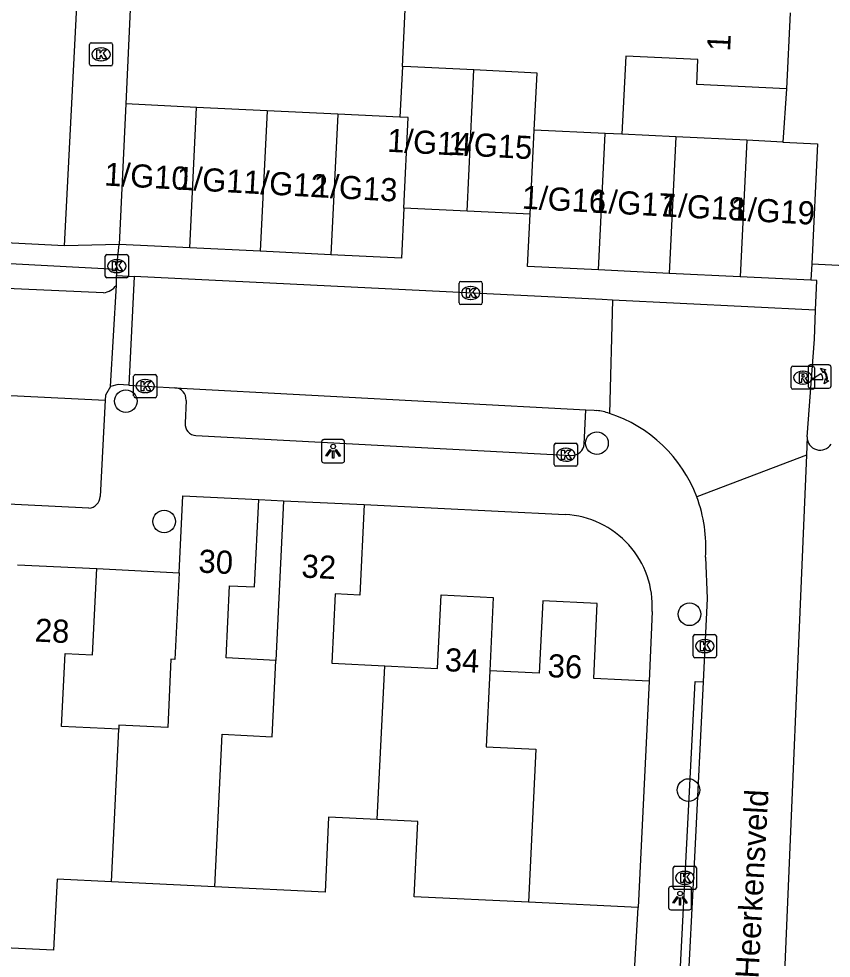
# Model space of a CAD drawing. Extents: x 162990 to 165007, y 383433 to 384336.
# Drawn here: x 164423.42 to 164458.56, y 383752.31 to 383792.95 of the extents above; entities that cross this region are included whole.
import ezdxf

# ---------------------------------------------------------------- set-up
doc = ezdxf.new("R2010")
doc.units = 0
for name, color, linetype in [('IMGEO_Boom', 7, 'Continuous'), ('IMGEO_Kolk', 7, 'Continuous'), ('IMGEO_Lichtpunt', 7, 'Continuous'), ('IMGEO_Muur', 7, 'Continuous'), ('IMGEO_Openbare_ruimte_label', 7, 'Continuous'), ('IMGEO_Pand', 7, 'Continuous'), ('IMGEO_Pand_nummerreeks', 7, 'Continuous'), ('IMGEO_Poller', 7, 'Continuous'), ('IMGEO_Rijbaan_lokaal_open', 7, 'Continuous'), ('IMGEO_Rioolput', 7, 'Continuous'), ('IMGEO_Voetpad_open', 7, 'Continuous')]:
    doc.layers.add(name, color=color, linetype=linetype)

msp = doc.modelspace()

# ---------------------------------------------------------------- linework, layer by layer
at = {"layer": 'IMGEO_Boom'}
for centre in [(164428.046, 383776.408), (164448.428, 383774.593), (164429.703, 383771.203), (164452.433, 383767.192), (164452.385, 383759.588)]:
    msp.add_circle(centre, 0.489, dxfattribs=at)
at = {"layer": 'IMGEO_Kolk'}
for p, q in [((164426.551, 383791.916), (164427.403, 383791.916)), ((164426.476, 383790.99), (164426.476, 383791.842)), ((164426.964, 383791.696), (164426.989, 383791.696)), ((164427.477, 383791.842), (164427.477, 383790.99)), ((164426.987, 383791.136), (164426.962, 383791.136)), ((164427.403, 383790.916), (164426.551, 383790.916)), ((164427.156, 383781.825), (164427.156, 383782.677)), ((164427.231, 383782.751), (164428.083, 383782.751)), ((164428.157, 383782.677), (164428.157, 383781.825)), ((164427.644, 383782.531), (164427.669, 383782.531)), ((164428.083, 383781.751), (164427.231, 383781.751)), ((164427.667, 383781.971), (164427.642, 383781.971)), ((164442.465, 383780.663), (164442.465, 383781.515)), ((164442.54, 383781.589), (164443.392, 383781.589)), ((164442.953, 383781.369), (164442.978, 383781.369)), ((164443.466, 383781.515), (164443.466, 383780.663)), ((164443.392, 383780.589), (164442.54, 383780.589)), ((164442.976, 383780.809), (164442.951, 383780.809)), ((164428.387, 383776.636), (164428.387, 383777.488)), ((164428.462, 383777.562), (164429.314, 383777.562)), ((164428.875, 383777.342), (164428.9, 383777.342)), ((164429.388, 383777.488), (164429.388, 383776.636)), ((164429.314, 383776.562), (164428.462, 383776.562)), ((164428.898, 383776.782), (164428.873, 383776.782)), ((164446.58, 383773.667), (164446.58, 383774.519)), ((164446.655, 383774.593), (164447.507, 383774.593)), ((164447.581, 383774.519), (164447.581, 383773.667)), ((164447.068, 383774.373), (164447.093, 383774.373)), ((164447.091, 383773.813), (164447.066, 383773.813)), ((164447.507, 383773.593), (164446.655, 383773.593)), ((164452.667, 383766.314), (164453.519, 383766.314)), ((164452.592, 383765.388), (164452.592, 383766.24)), ((164453.08, 383766.094), (164453.105, 383766.094)), ((164453.593, 383766.24), (164453.593, 383765.388)), ((164453.103, 383765.534), (164453.078, 383765.534)), ((164453.519, 383765.314), (164452.667, 383765.314)), ((164451.728, 383755.365), (164451.728, 383756.217)), ((164451.803, 383756.291), (164452.655, 383756.291)), ((164452.729, 383756.217), (164452.729, 383755.365)), ((164452.216, 383756.071), (164452.241, 383756.071)), ((164452.239, 383755.511), (164452.214, 383755.511)), ((164452.655, 383755.291), (164451.803, 383755.291))]:
    msp.add_line(p, q, dxfattribs=at)
for points in [[(164426.551, 383791.916), (164427.403, 383791.916)], [(164426.476, 383790.99), (164426.476, 383791.842)], [(164426.797, 383791.616), (164426.92, 383791.616), (164426.92, 383791.465), (164427.05, 383791.616), (164427.214, 383791.616), (164427.068, 383791.465), (164427.221, 383791.216), (164427.069, 383791.216), (164426.984, 383791.38), (164426.92, 383791.313), (164426.92, 383791.216), (164426.797, 383791.216), (164426.797, 383791.616)], [(164427.477, 383791.842), (164427.477, 383790.99)], [(164427.403, 383790.916), (164426.551, 383790.916)], [(164427.156, 383781.825), (164427.156, 383782.677)], [(164427.231, 383782.751), (164428.083, 383782.751)], [(164428.157, 383782.677), (164428.157, 383781.825)], [(164427.477, 383782.451), (164427.6, 383782.451), (164427.6, 383782.3), (164427.73, 383782.451), (164427.894, 383782.451), (164427.748, 383782.3), (164427.901, 383782.051), (164427.749, 383782.051), (164427.664, 383782.215), (164427.6, 383782.148), (164427.6, 383782.051), (164427.477, 383782.051), (164427.477, 383782.451)], [(164428.083, 383781.751), (164427.231, 383781.751)], [(164442.465, 383780.663), (164442.465, 383781.515)], [(164442.54, 383781.589), (164443.392, 383781.589)], [(164443.466, 383781.515), (164443.466, 383780.663)], [(164442.786, 383781.289), (164442.909, 383781.289), (164442.909, 383781.138), (164443.039, 383781.289), (164443.203, 383781.289), (164443.057, 383781.138), (164443.21, 383780.889), (164443.058, 383780.889), (164442.973, 383781.053), (164442.909, 383780.986), (164442.909, 383780.889), (164442.786, 383780.889), (164442.786, 383781.289)], [(164443.392, 383780.589), (164442.54, 383780.589)], [(164428.387, 383776.636), (164428.387, 383777.488)], [(164428.462, 383777.562), (164429.314, 383777.562)], [(164429.388, 383777.488), (164429.388, 383776.636)], [(164428.708, 383777.262), (164428.831, 383777.262), (164428.831, 383777.111), (164428.961, 383777.262), (164429.125, 383777.262), (164428.979, 383777.111), (164429.132, 383776.862), (164428.98, 383776.862), (164428.895, 383777.026), (164428.831, 383776.959), (164428.831, 383776.862), (164428.708, 383776.862), (164428.708, 383777.262)], [(164429.314, 383776.562), (164428.462, 383776.562)], [(164446.58, 383773.667), (164446.58, 383774.519)], [(164446.655, 383774.593), (164447.507, 383774.593)], [(164447.581, 383774.519), (164447.581, 383773.667)], [(164446.901, 383774.293), (164447.024, 383774.293), (164447.024, 383774.142), (164447.154, 383774.293), (164447.318, 383774.293), (164447.172, 383774.142), (164447.325, 383773.893), (164447.173, 383773.893), (164447.088, 383774.057), (164447.024, 383773.99), (164447.024, 383773.893), (164446.901, 383773.893), (164446.901, 383774.293)], [(164447.507, 383773.593), (164446.655, 383773.593)], [(164452.667, 383766.314), (164453.519, 383766.314)], [(164452.592, 383765.388), (164452.592, 383766.24)], [(164452.913, 383766.014), (164453.036, 383766.014), (164453.036, 383765.863), (164453.166, 383766.014), (164453.33, 383766.014), (164453.184, 383765.863), (164453.337, 383765.614), (164453.185, 383765.614), (164453.1, 383765.778), (164453.036, 383765.711), (164453.036, 383765.614), (164452.913, 383765.614), (164452.913, 383766.014)], [(164453.593, 383766.24), (164453.593, 383765.388)], [(164453.519, 383765.314), (164452.667, 383765.314)], [(164451.728, 383755.365), (164451.728, 383756.217)], [(164451.803, 383756.291), (164452.655, 383756.291)], [(164452.729, 383756.217), (164452.729, 383755.365)], [(164452.049, 383755.991), (164452.172, 383755.991), (164452.172, 383755.84), (164452.302, 383755.991), (164452.466, 383755.991), (164452.32, 383755.84), (164452.473, 383755.591), (164452.321, 383755.591), (164452.236, 383755.755), (164452.172, 383755.688), (164452.172, 383755.591), (164452.049, 383755.591), (164452.049, 383755.991)], [(164452.655, 383755.291), (164451.803, 383755.291)]]:
    msp.add_lwpolyline(points, dxfattribs=at)
for centre, start, end in [((164426.553, 383791.84), 91.552, 178.448), ((164426.553, 383791.84), 91.552, 178.448), ((164427.401, 383791.84), 1.552, 88.448), ((164427.401, 383791.84), 1.552, 88.448), ((164426.553, 383790.992), 181.552, 268.448), ((164426.553, 383790.992), 181.552, 268.448), ((164427.401, 383790.992), 271.552, 358.448), ((164427.401, 383790.992), 271.552, 358.448), ((164427.233, 383782.675), 91.552, 178.448), ((164427.233, 383782.675), 91.552, 178.448), ((164428.081, 383782.675), 1.552, 88.448), ((164428.081, 383782.675), 1.552, 88.448), ((164427.233, 383781.827), 181.552, 268.448), ((164427.233, 383781.827), 181.552, 268.448), ((164428.081, 383781.827), 271.552, 358.448), ((164428.081, 383781.827), 271.552, 358.448), ((164442.542, 383781.513), 91.552, 178.448), ((164442.542, 383781.513), 91.552, 178.448), ((164443.39, 383781.513), 1.552, 88.448), ((164443.39, 383781.513), 1.552, 88.448), ((164442.542, 383780.665), 181.552, 268.448), ((164442.542, 383780.665), 181.552, 268.448), ((164443.39, 383780.665), 271.552, 358.448), ((164443.39, 383780.665), 271.552, 358.448), ((164428.464, 383777.486), 91.552, 178.448), ((164428.464, 383777.486), 91.552, 178.448), ((164429.312, 383777.486), 1.552, 88.448), ((164429.312, 383777.486), 1.552, 88.448), ((164428.464, 383776.638), 181.552, 268.448), ((164428.464, 383776.638), 181.552, 268.448), ((164429.312, 383776.638), 271.552, 358.448), ((164429.312, 383776.638), 271.552, 358.448), ((164446.657, 383774.517), 91.552, 178.448), ((164446.657, 383774.517), 91.552, 178.448), ((164447.505, 383774.517), 1.552, 88.448), ((164447.505, 383774.517), 1.552, 88.448), ((164446.657, 383773.669), 181.552, 268.448), ((164446.657, 383773.669), 181.552, 268.448), ((164447.505, 383773.669), 271.552, 358.448), ((164447.505, 383773.669), 271.552, 358.448), ((164452.669, 383766.238), 91.552, 178.448), ((164452.669, 383766.238), 91.552, 178.448), ((164453.517, 383766.238), 1.552, 88.448), ((164453.517, 383766.238), 1.552, 88.448), ((164452.669, 383765.39), 181.552, 268.448), ((164452.669, 383765.39), 181.552, 268.448), ((164453.517, 383765.39), 271.552, 358.448), ((164453.517, 383765.39), 271.552, 358.448), ((164451.805, 383756.215), 91.552, 178.448), ((164451.805, 383756.215), 91.552, 178.448), ((164452.653, 383756.215), 1.552, 88.448), ((164452.653, 383756.215), 1.552, 88.448), ((164451.805, 383755.367), 181.552, 268.448), ((164451.805, 383755.367), 181.552, 268.448), ((164452.653, 383755.367), 271.552, 358.448), ((164452.653, 383755.367), 271.552, 358.448)]:
    msp.add_arc(centre, 0.0765, start, end, dxfattribs=at)
for centre, major_axis, ratio, start_param, end_param in [((164426.963, 383791.416), (-0.387, 0.002), 0.722429, 4.712389, 7.853982), ((164426.988, 383791.416), (-0.39, 0.002), 0.717154, 1.570796, 4.712389), ((164427.643, 383782.251), (-0.387, 0.002), 0.722429, 4.712389, 7.853982), ((164427.668, 383782.251), (-0.39, 0.002), 0.717154, 1.570796, 4.712389), ((164442.952, 383781.089), (-0.387, 0.002), 0.722429, 4.712389, 7.853982), ((164442.977, 383781.089), (-0.39, 0.002), 0.717154, 1.570796, 4.712389), ((164428.874, 383777.062), (-0.387, 0.002), 0.722429, 4.712389, 7.853982), ((164428.899, 383777.062), (-0.39, 0.002), 0.717154, 1.570796, 4.712389), ((164447.067, 383774.093), (-0.387, 0.002), 0.722429, 4.712389, 7.853982), ((164447.092, 383774.093), (-0.39, 0.002), 0.717154, 1.570796, 4.712389), ((164453.079, 383765.814), (-0.387, 0.002), 0.722429, 4.712389, 7.853982), ((164453.104, 383765.814), (-0.39, 0.002), 0.717154, 1.570796, 4.712389), ((164452.215, 383755.791), (-0.387, 0.002), 0.722429, 4.712389, 7.853982), ((164452.24, 383755.791), (-0.39, 0.002), 0.717154, 1.570796, 4.712389)]:
    msp.add_ellipse(centre, major_axis=major_axis, ratio=ratio, start_param=start_param, end_param=end_param, dxfattribs=at)
at = {"layer": 'IMGEO_Lichtpunt'}
for p, q in [((164436.516, 383774.651), (164436.516, 383773.844)), ((164436.516, 383774.651), (164436.516, 383773.844)), ((164437.418, 383774.746), (164436.61, 383774.746)), ((164437.418, 383774.746), (164436.61, 383774.746)), ((164437.512, 383773.844), (164437.512, 383774.651)), ((164437.512, 383773.844), (164437.512, 383774.651)), ((164436.61, 383773.75), (164437.418, 383773.75)), ((164436.61, 383773.75), (164437.418, 383773.75)), ((164452.427, 383755.409), (164451.619, 383755.409)), ((164452.427, 383755.409), (164451.619, 383755.409)), ((164451.525, 383755.314), (164451.525, 383754.507)), ((164451.525, 383755.314), (164451.525, 383754.507)), ((164452.521, 383754.507), (164452.521, 383755.314)), ((164452.521, 383754.507), (164452.521, 383755.314)), ((164451.619, 383754.413), (164452.427, 383754.413)), ((164451.619, 383754.413), (164452.427, 383754.413))]:
    msp.add_line(p, q, dxfattribs=at)
for points in [[(164436.89, 383774.315), (164436.929, 383774.287), (164436.741, 383774.025), (164436.703, 383774.052), (164436.89, 383774.315)], [(164436.992, 383774.267), (164437.039, 383774.267), (164437.039, 383773.945), (164436.992, 383773.945), (164436.992, 383774.267)], [(164437.102, 383774.287), (164437.14, 383774.314), (164437.327, 383774.052), (164437.288, 383774.024), (164437.102, 383774.287)], [(164451.899, 383754.978), (164451.938, 383754.95), (164451.75, 383754.688), (164451.712, 383754.715), (164451.899, 383754.978)], [(164452.001, 383754.93), (164452.048, 383754.93), (164452.048, 383754.608), (164452.001, 383754.608), (164452.001, 383754.93)], [(164452.111, 383754.95), (164452.149, 383754.977), (164452.336, 383754.715), (164452.297, 383754.687), (164452.111, 383754.95)]]:
    msp.add_lwpolyline(points, dxfattribs=at)
for centre in [(164437.015, 383774.449), (164452.024, 383755.112)]:
    msp.add_circle(centre, 0.0994, dxfattribs=at)
for centre, start, end in [((164436.61, 383774.651), 90, 180), ((164436.61, 383774.651), 90, 180), ((164437.418, 383774.651), 0, 90), ((164437.418, 383774.651), 0, 90), ((164436.61, 383773.844), 180, 270), ((164436.61, 383773.844), 180, 270), ((164437.418, 383773.844), 270, 0), ((164437.418, 383773.844), 270, 360), ((164451.619, 383755.314), 90, 180), ((164451.619, 383755.314), 90, 180), ((164452.427, 383755.314), 0, 90), ((164452.427, 383755.314), 0, 90), ((164451.619, 383754.507), 180, 270), ((164451.619, 383754.507), 180, 270), ((164452.427, 383754.507), 270, 0), ((164452.427, 383754.507), 270, 360)]:
    msp.add_arc(centre, 0.0946, start, end, dxfattribs=at)
at = {"layer": 'IMGEO_Muur'}
for points in [[(164448.304, 383707.855), (164448.207, 383705.364), (164447.887, 383705.375), (164448.047, 383709.634), (164444.948, 383709.752), (164445.705, 383725.181), (164445.823, 383727.577), (164446.336, 383738.034), (164448.318, 383737.931), (164451.313, 383737.776), (164451.421, 383739.875), (164451.942, 383750), (164452.677, 383764.285), (164453.018, 383764.265)], [(164453.018, 383764.265), (164452.659, 383756.974), (164452.307, 383750), (164452.117, 383746.236)]]:
    msp.add_lwpolyline(points, dxfattribs=at)
at = {"layer": 'IMGEO_Pand'}
for points in [[(164440.011, 383790.885), (164440.251, 383795.847)], [(164456.792, 383793.213), (164456.633, 383789.929)], [(164456.633, 383789.929), (164452.745, 383790.117), (164452.797, 383791.191), (164449.67, 383791.342), (164449.505, 383787.957)], [(164440.011, 383790.885), (164439.905, 383788.696)], [(164443.101, 383790.738), (164440.374, 383790.868), (164440.011, 383790.885)], [(164442.81, 383784.635), (164443.101, 383790.738)], [(164445.716, 383788.136), (164445.836, 383790.608), (164443.101, 383790.738)], [(164428.052, 383789.269), (164427.758, 383783.191)], [(164431.106, 383789.121), (164428.052, 383789.269)], [(164430.812, 383783.044), (164431.106, 383789.121)], [(164434.16, 383788.974), (164431.106, 383789.121)], [(164434.16, 383788.974), (164433.866, 383782.896)], [(164437.214, 383788.826), (164434.16, 383788.974)], [(164437.214, 383788.826), (164436.92, 383782.748)], [(164439.905, 383788.696), (164437.214, 383788.826)], [(164440.079, 383784.767), (164440.268, 383788.678), (164439.905, 383788.696)], [(164445.54, 383784.503), (164445.716, 383788.136)], [(164448.779, 383787.991), (164445.716, 383788.136)], [(164448.493, 383782.086), (164448.779, 383787.991)], [(164449.505, 383787.957), (164448.779, 383787.991)], [(164451.842, 383787.844), (164449.505, 383787.957)], [(164451.842, 383787.844), (164451.556, 383781.938)], [(164454.905, 383787.696), (164451.842, 383787.844)], [(164454.905, 383787.696), (164454.62, 383781.79)], [(164456.468, 383787.62), (164454.905, 383787.696)], [(164456.468, 383787.62), (164457.968, 383787.548), (164457.717, 383782.349)], [(164440.079, 383784.767), (164439.974, 383782.601), (164436.92, 383782.748)], [(164442.81, 383784.635), (164440.079, 383784.767)], [(164445.54, 383784.503), (164442.81, 383784.635)], [(164448.493, 383782.086), (164445.43, 383782.234), (164445.54, 383784.503)], [(164430.812, 383783.044), (164427.758, 383783.191)], [(164433.866, 383782.896), (164430.812, 383783.044)], [(164436.92, 383782.748), (164433.866, 383782.896)], [(164457.717, 383782.349), (164457.683, 383781.642)], [(164451.556, 383781.938), (164448.493, 383782.086)], [(164454.62, 383781.79), (164451.556, 383781.938)], [(164457.683, 383781.642), (164454.62, 383781.79)], [(164430.353, 383768.988), (164430.514, 383772.316), (164433.798, 383772.157)], [(164434.539, 383765.198), (164432.387, 383765.302), (164432.538, 383768.427), (164433.615, 383768.375), (164433.798, 383772.157)], [(164434.873, 383772.105), (164434.539, 383765.198)], [(164434.873, 383772.105), (164438.364, 383771.936)], [(164438.364, 383771.936), (164438.174, 383768.018), (164437.104, 383768.07), (164436.959, 383765.074), (164439.248, 383764.963)], [(164423.364, 383769.334), (164426.791, 383769.168)], [(164427.744, 383762.219), (164425.267, 383762.339), (164425.419, 383765.489), (164426.61, 383765.432), (164426.791, 383769.168)], [(164430.353, 383768.988), (164430.171, 383765.236), (164430.001, 383765.244), (164429.858, 383762.287), (164427.752, 383762.389), (164427.744, 383762.219)], [(164439.248, 383764.963), (164441.533, 383764.852), (164441.687, 383768.026), (164443.944, 383767.916), (164443.791, 383764.746)], [(164450.688, 383764.303), (164448.287, 383764.419), (164448.443, 383767.657), (164446.085, 383767.771), (164445.934, 383764.642), (164443.791, 383764.746)], [(164431.894, 383755.4), (164432.222, 383762.004), (164434.38, 383761.897), (164434.539, 383765.198)], [(164438.927, 383758.309), (164439.248, 383764.963)], [(164443.791, 383764.746), (164443.629, 383761.453), (164445.777, 383761.35), (164445.46, 383754.732)], [(164450.688, 383764.303), (164450.213, 383754.502)], [(164427.424, 383755.616), (164427.744, 383762.219)], [(164438.927, 383758.309), (164436.821, 383758.411), (164436.664, 383755.169), (164431.894, 383755.4)], [(164445.46, 383754.732), (164440.522, 383754.971), (164440.679, 383758.224), (164438.927, 383758.309)], [(164427.424, 383755.616), (164425.072, 383755.73), (164424.923, 383752.656), (164420.371, 383752.876)], [(164431.894, 383755.4), (164427.424, 383755.616)], [(164450.213, 383754.502), (164445.46, 383754.732)]]:
    msp.add_lwpolyline(points, dxfattribs=at)
at = {"layer": 'IMGEO_Poller'}
for p, q in [((164457.56, 383777.881), (164457.56, 383777.074)), ((164457.56, 383777.881), (164457.56, 383777.074)), ((164458.462, 383777.976), (164457.654, 383777.976)), ((164458.462, 383777.976), (164457.654, 383777.976)), ((164458.556, 383777.074), (164458.556, 383777.881)), ((164458.556, 383777.074), (164458.556, 383777.881)), ((164457.654, 383776.979), (164458.462, 383776.979)), ((164457.654, 383776.979), (164458.462, 383776.979))]:
    msp.add_line(p, q, dxfattribs=at)
for points in [[(164458.239, 383777.705), (164458.227, 383777.632), (164458.102, 383777.837)], [(164458.102, 383777.837), (164458.333, 383777.771), (164458.262, 383777.739)], [(164458.195, 383777.332), (164457.682, 383777.332), (164458.112, 383777.607)], [(164458.255, 383777.16), (164458.321, 383777.391), (164458.351, 383777.323)], [(164458.387, 383777.296), (164458.459, 383777.285), (164458.255, 383777.16)]]:
    msp.add_lwpolyline(points, dxfattribs=at)
for centre, radius, start, end in [((164457.654, 383777.881), 0.0946, 90, 180), ((164457.654, 383777.881), 0.0946, 90, 180), ((164457.881, 383777.392), 0.476, 351.7527, 41.1691), ((164457.881, 383777.392), 0.516, 349.3569, 42.2912), ((164458.462, 383777.881), 0.0946, 0, 90), ((164458.462, 383777.881), 0.0946, 0, 90), ((164457.867, 383777.382), 0.332, 351.3247, 42.4854), ((164457.654, 383777.074), 0.0946, 180, 270), ((164457.654, 383777.074), 0.0946, 180, 270), ((164458.462, 383777.074), 0.0946, 270, 0), ((164458.462, 383777.074), 0.0946, 270, 0)]:
    msp.add_arc(centre, radius, start, end, dxfattribs=at)
at = {"layer": 'IMGEO_Rijbaan_lokaal_open'}
for points in [[(164427.648, 383781.429), (164427.645, 383781.849)], [(164427.645, 383781.849), (164428.402, 383781.811)], [(164428.402, 383781.811), (164428.174, 383777.103)], [(164449.106, 383780.783), (164448.655, 383780.805), (164428.402, 383781.811)], [(164427.083, 383781.092), (164421.584, 383781.337)], [(164427.39, 383777.043), (164427.648, 383781.429)], [(164449.106, 383780.783), (164448.964, 383775.88)], [(164457.884, 383780.347), (164449.106, 383780.783)], [(164457.521, 383774.867), (164457.837, 383779.095), (164457.884, 383780.347)], [(164397.078, 383777.936), (164427.158, 383776.448)], [(164427.39, 383777.043), (164427.17, 383776.67), (164427.158, 383776.448)], [(164428.174, 383777.103), (164427.718, 383777.128), (164427.39, 383777.043)], [(164428.174, 383777.103), (164430.166, 383776.992)], [(164430.166, 383776.992), (164447.951, 383776.037)], [(164447.951, 383776.037), (164448.308, 383776.018), (164448.42, 383776.008)], [(164457.521, 383774.867), (164457.488, 383774.081)], [(164457.488, 383774.081), (164452.748, 383772.269)], [(164457.488, 383774.081), (164456.472, 383750), (164456.32, 383746.862)], [(164453.122, 383769.665), (164453.196, 383767.88), (164453.018, 383764.265)]]:
    msp.add_lwpolyline(points, dxfattribs=at)
for centre, radius, start, end in [((164426.929, 383781.993), 0.914, 279.7268, 321.902), ((164448.161, 383773.687), 2.335, 69.8868, 83.6322), ((164447.085, 383770.123), 6.056, 20.7557, 71.9246), ((164446.94, 383770.106), 6.198, 355.9206, 20.4258)]:
    msp.add_arc(centre, radius, start, end, dxfattribs=at)
at = {"layer": 'IMGEO_Rioolput'}
for p, q in [((164456.833, 383777.002), (164456.833, 383777.854)), ((164456.908, 383777.928), (164457.76, 383777.928)), ((164457.321, 383777.708), (164457.346, 383777.708)), ((164457.834, 383777.854), (164457.834, 383777.002)), ((164457.76, 383776.928), (164456.908, 383776.928)), ((164457.344, 383777.148), (164457.319, 383777.148))]:
    msp.add_line(p, q, dxfattribs=at)
for points in [[(164456.833, 383777.002), (164456.833, 383777.854)], [(164456.908, 383777.928), (164457.76, 383777.928)], [(164457.834, 383777.854), (164457.834, 383777.002)], [(164457.422, 383777.626), (164457.17, 383777.628), (164457.17, 383777.228)], [(164457.17, 383777.228), (164457.294, 383777.228), (164457.294, 383777.39), (164457.305, 383777.39)], [(164457.348, 383777.547), (164457.294, 383777.547), (164457.294, 383777.466)], [(164457.294, 383777.466), (164457.346, 383777.466)], [(164457.352, 383777.361), (164457.423, 383777.228), (164457.563, 383777.228), (164457.498, 383777.354)], [(164457.76, 383776.928), (164456.908, 383776.928)]]:
    msp.add_lwpolyline(points, dxfattribs=at)
for centre, radius, start, end in [((164456.91, 383777.852), 0.0765, 91.552, 178.448), ((164456.91, 383777.852), 0.0765, 91.552, 178.448), ((164457.758, 383777.852), 0.0765, 1.552, 88.448), ((164457.758, 383777.852), 0.0765, 1.552, 88.448), ((164457.304, 383777.337), 0.0533, 26.0293, 88.6989), ((164457.33, 383777.655), 0.19, 274.7715, 282.9687), ((164457.354, 383777.451), 0.0964, 77.0061, 93.1865), ((164457.368, 383777.508), 0.0378, 276.6634, 79.6772), ((164457.421, 383777.516), 0.109, 350.3612, 89.416), ((164457.419, 383777.516), 0.112, 277.5842, 350.9817), ((164457.403, 383777.301), 0.108, 29.5134, 73.7905), ((164456.91, 383777.004), 0.0765, 181.552, 268.448), ((164456.91, 383777.004), 0.0765, 181.552, 268.448), ((164457.758, 383777.004), 0.0765, 271.552, 358.448), ((164457.758, 383777.004), 0.0765, 271.552, 358.448)]:
    msp.add_arc(centre, radius, start, end, dxfattribs=at)
for centre, major_axis, ratio, start_param, end_param in [((164457.32, 383777.428), (-0.387, 0.002), 0.722429, 4.712389, 7.853982), ((164457.345, 383777.428), (-0.39, 0.002), 0.717154, 1.570796, 4.712389)]:
    msp.add_ellipse(centre, major_axis=major_axis, ratio=ratio, start_param=start_param, end_param=end_param, dxfattribs=at)
at = {"layer": 'IMGEO_Voetpad_open'}
for points in [[(164425.399, 383783.128), (164426.912, 383812.576), (164431.451, 383812.384), (164431.928, 383821.375)], [(164433.462, 383814.057), (164433.012, 383805.061), (164428.784, 383805.303), (164428.052, 383789.269)], [(164456.633, 383789.929), (164456.468, 383787.62)], [(164425.399, 383783.128), (164421.706, 383783.313)], [(164427.758, 383783.191), (164425.399, 383783.128)], [(164427.643, 383782.119), (164427.758, 383783.191)], [(164421.662, 383782.446), (164427.643, 383782.119)], [(164457.717, 383782.349), (164463.485, 383782.07)], [(164427.643, 383782.119), (164427.645, 383781.849)], [(164457.884, 383780.347), (164457.933, 383781.63), (164457.683, 383781.642)], [(164427.158, 383776.448), (164426.94, 383772.28)], [(164430.654, 383776.446), (164430.611, 383775.458)], [(164447.881, 383774.544), (164447.951, 383776.037)], [(164431.082, 383774.927), (164447.343, 383774.063)], [(164426.446, 383771.778), (164397.588, 383773.205)], [(164433.798, 383772.157), (164434.873, 383772.105)], [(164438.364, 383771.936), (164447.055, 383771.509)], [(164426.791, 383769.168), (164430.353, 383768.988)], [(164450.817, 383767.317), (164450.688, 383764.303)], [(164449.699, 383745.793), (164449.947, 383750), (164450.213, 383754.502)]]:
    msp.add_lwpolyline(points, dxfattribs=at)
for centre, radius, start, end in [((164430.133, 383776.472), 0.522, 357.1954, 86.3836), ((164431.108, 383775.424), 0.498, 176.0851, 267.0613), ((164458.084, 383774.855), 0.563, 178.7586, 327.843), ((164447.335, 383774.613), 0.55, 270.7989, 352.7978), ((164426.4, 383772.318), 0.542, 274.903, 356.0174), ((164446.841, 383767.533), 3.982, 356.8878, 86.9233)]:
    msp.add_arc(centre, radius, start, end, dxfattribs=at)

# ---------------------------------------------------------------- texts
at = {"layer": 'IMGEO_Openbare_ruimte_label'}
msp.add_text('Heerkensveld', height=1, rotation=86.9059, dxfattribs=at).set_placement((164455.41, 383751.42))
at = {"layer": 'IMGEO_Pand_nummerreeks'}
for s, rotation, p in [('1', 87.2281, (164454.187, 383791.532)), ('1/G14', 356.8315, (164439.338, 383787.204)), ('1/G15', 356.8312, (164441.965, 383787.077)), ('1/G10', 356.8312, (164427.102, 383785.743)), ('1/G11', 356.8312, (164430.219, 383785.57)), ('1/G12', 356.8312, (164433.113, 383785.41)), ('1/G13', 356.8315, (164436.13, 383785.243)), ('1/G16', 356.8312, (164445.161, 383784.743)), ('1/G17', 356.8312, (164448.171, 383784.576)), ('1/G18', 356.8312, (164451.185, 383784.409)), ('1/G19', 356.8315, (164454.19, 383784.243)), ('30', 357.2281, (164431.175, 383769)), ('32', 357.2285, (164435.631, 383768.784)), ('28', 357.2268, (164424.096, 383766.014)), ('34', 357.2098, (164441.83, 383764.734)), ('36', 357.2321, (164446.28, 383764.477))]:
    msp.add_text(s, height=1, rotation=rotation, dxfattribs=at).set_placement(p)

doc.saveas('drawing.dxf')
